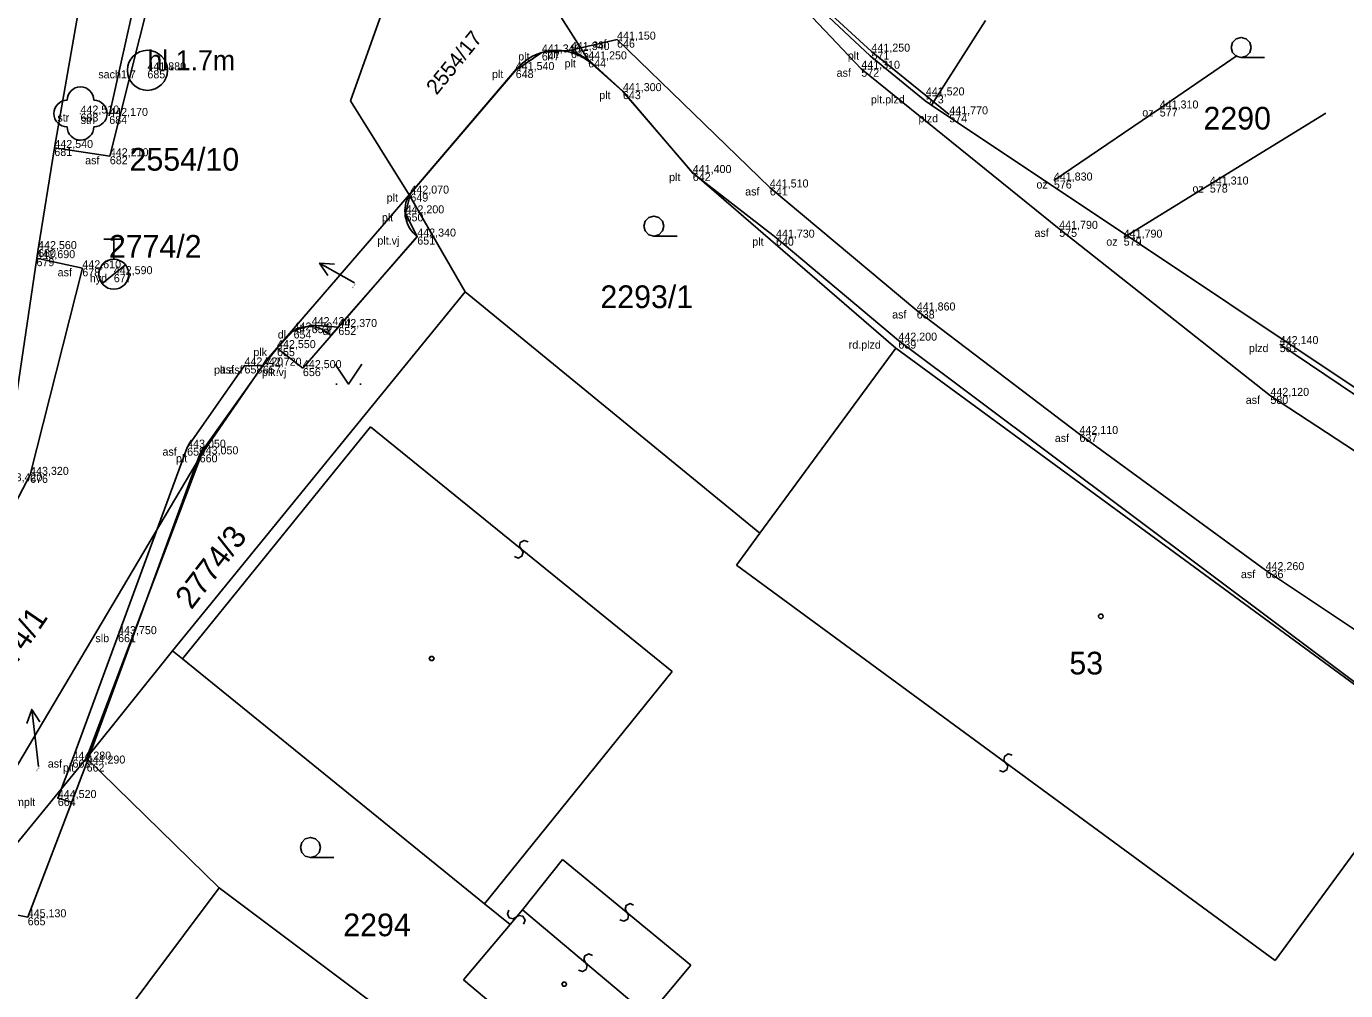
# Model space of a CAD drawing. Extents: x -747792 to -745414, y -1093712 to -1091463.
# Drawn here: x -746697.99 to -746648.52, y -1093147.3 to -1093111.16 of the extents above; entities that cross this region are included whole.
import ezdxf

# ---------------------------------------------------------------- set-up
doc = ezdxf.new("R2010")
doc.units = 0
for name, color, linetype in [('Budovy', 7, 'Continuous'), ('Doplňkové značky', 7, 'Continuous'), ('Hladina', 7, 'Continuous'), ('Koleje_dopravní prvky', 7, 'Continuous'), ('Kultury', 7, 'Continuous'), ('Nezařazené objekty', 7, 'Continuous'), ('Nivelační značky_hrany', 7, 'Continuous'), ('Ploty_opěrné zdi', 7, 'Continuous'), ('Popisy objektů_povrchů', 7, 'Continuous'), ('Pracovní_bod JDTM STC_VC - výška', 7, 'Continuous'), ('Pracovní_bod PPBP - výška', 7, 'Continuous'), ('Pracovní_bod ZPBP - číslo', 7, 'Continuous'), ('Rozhraní ploch', 7, 'Continuous'), ('Stromy_porost', 7, 'Continuous'), ('Výškopis', 7, 'Continuous'), ('Čísla popisná_parcelní', 7, 'Continuous')]:
    doc.layers.add(name, color=color, linetype=linetype)

msp = doc.modelspace()

# ---------------------------------------------------------------- linework, layer by layer
at = {"layer": 'Budovy'}
for points in [[(-746652.44, -1093112.33), (-746652.63, -1093112.28), (-746652.765, -1093112.14), (-746652.815, -1093111.955), (-746652.765, -1093111.77), (-746652.63, -1093111.63), (-746652.44, -1093111.58), (-746652.25, -1093111.63), (-746652.115, -1093111.77), (-746652.065, -1093111.955), (-746652.115, -1093112.14), (-746652.25, -1093112.28), (-746652.44, -1093112.33), (-746651.565, -1093112.33)], [(-746674.46, -1093119.02), (-746674.65, -1093118.97), (-746674.785, -1093118.83), (-746674.835, -1093118.645), (-746674.785, -1093118.46), (-746674.65, -1093118.32), (-746674.46, -1093118.27), (-746674.27, -1093118.32), (-746674.135, -1093118.46), (-746674.085, -1093118.645), (-746674.135, -1093118.83), (-746674.27, -1093118.97), (-746674.46, -1093119.02), (-746673.585, -1093119.02)], [(-746686.41, -1093123.82), (-746685.91, -1093124.57), (-746685.41, -1093123.82)], [(-746686.385, -1093124.57), (-746686.335, -1093124.57)], [(-746685.485, -1093124.57), (-746685.435, -1093124.57)], [(-746687.34, -1093142.31), (-746687.53, -1093142.26), (-746687.665, -1093142.12), (-746687.715, -1093141.935), (-746687.665, -1093141.75), (-746687.53, -1093141.61), (-746687.34, -1093141.56), (-746687.15, -1093141.61), (-746687.015, -1093141.75), (-746686.965, -1093141.935), (-746687.015, -1093142.12), (-746687.15, -1093142.26), (-746687.34, -1093142.31), (-746686.465, -1093142.31)]]:
    msp.add_lwpolyline(points, dxfattribs=at)
at = {"layer": 'Doplňkové značky'}
for points in [[(-746686.996, -1093120.041), (-746685.69, -1093120.78)], [(-746686.683, -1093120.505), (-746686.996, -1093120.041), (-746686.437, -1093120.07)], [(-746697.978, -1093137.287), (-746697.79, -1093136.761), (-746697.482, -1093137.227)], [(-746697.79, -1093136.761), (-746697.61, -1093138.25)], [(-746697.54, -1093138.9), (-746697.61, -1093138.25)]]:
    msp.add_lwpolyline(points, dxfattribs=at)
at = {"layer": 'Hladina'}
for p, q in [((-746677.57, -1093112.05), (-746677.57, -1093112.05)), ((-746675.84, -1093111.66), (-746675.84, -1093111.66)), ((-746666.3, -1093112.11), (-746666.3, -1093112.11)), ((-746678.66, -1093112.14), (-746678.66, -1093112.14)), ((-746676.92, -1093112.4), (-746676.92, -1093112.4)), ((-746693.45, -1093112.81), (-746693.45, -1093112.81)), ((-746679.64, -1093112.8), (-746679.64, -1093112.8)), ((-746666.68, -1093112.75), (-746666.68, -1093112.75)), ((-746675.62, -1093113.59), (-746675.62, -1093113.59)), ((-746664.26, -1093113.75), (-746664.26, -1093113.75)), ((-746695.96, -1093114.43), (-746695.96, -1093114.43)), ((-746694.88, -1093114.52), (-746694.88, -1093114.52)), ((-746663.38, -1093114.46), (-746663.38, -1093114.46)), ((-746655.49, -1093114.24), (-746655.49, -1093114.24)), ((-746696.94, -1093115.72), (-746696.94, -1093115.72)), ((-746694.86, -1093116.03), (-746694.86, -1093116.03)), ((-746673, -1093116.66), (-746673, -1093116.66)), ((-746659.46, -1093116.94), (-746659.46, -1093116.94)), ((-746683.59, -1093117.43), (-746683.59, -1093117.43)), ((-746670.11, -1093117.2), (-746670.11, -1093117.2)), ((-746653.61, -1093117.09), (-746653.61, -1093117.09)), ((-746683.77, -1093118.17), (-746683.77, -1093118.17)), ((-746683.33, -1093119.04), (-746683.33, -1093119.04)), ((-746659.26, -1093118.75), (-746659.26, -1093118.75)), ((-746697.55, -1093119.51), (-746697.55, -1093119.51)), ((-746669.88, -1093119.08), (-746669.88, -1093119.08)), ((-746656.84, -1093119.08), (-746656.84, -1093119.08)), ((-746697.61, -1093119.85), (-746697.61, -1093119.85)), ((-746695.89, -1093120.23), (-746695.89, -1093120.23)), ((-746694.71, -1093120.45), (-746694.71, -1093120.45)), ((-746664.6, -1093121.81), (-746664.6, -1093121.81)), ((-746687.29, -1093122.36), (-746687.29, -1093122.36)), ((-746686.29, -1093122.43), (-746686.29, -1093122.43)), ((-746687.97, -1093122.56), (-746687.97, -1093122.56)), ((-746665.29, -1093122.94), (-746665.29, -1093122.94)), ((-746688.59, -1093123.22), (-746688.59, -1093123.22)), ((-746650.99, -1093123.07), (-746650.99, -1093123.07)), ((-746689.81, -1093123.87), (-746689.81, -1093123.87)), ((-746689.12, -1093123.88), (-746689.12, -1093123.88)), ((-746687.62, -1093123.97), (-746687.62, -1093123.97)), ((-746651.34, -1093125.01), (-746651.34, -1093125.01)), ((-746658.5, -1093126.44), (-746658.5, -1093126.44)), ((-746691.96, -1093126.95), (-746691.96, -1093126.95)), ((-746691.49, -1093127.2), (-746691.49, -1093127.2)), ((-746697.85, -1093127.97), (-746697.85, -1093127.97)), ((-746651.52, -1093131.54), (-746651.52, -1093131.54)), ((-746694.55, -1093133.94), (-746694.55, -1093133.94)), ((-746696.26, -1093138.64), (-746696.26, -1093138.64)), ((-746695.73, -1093138.79), (-746695.73, -1093138.79)), ((-746696.81, -1093140.08), (-746696.81, -1093140.08)), ((-746697.94, -1093144.55), (-746697.94, -1093144.55))]:
    msp.add_line(p, q, dxfattribs=at)
at = {"layer": 'Kultury'}
for points in [[(-746692.14, -1093134.87), (-746685.09, -1093126.17)], [(-746685.09, -1093126.17), (-746673.77, -1093135.34)], [(-746679.175, -1093130.479), (-746679.323, -1093130.424), (-746679.467, -1093130.506), (-746679.497, -1093130.655), (-746679.364, -1093130.873), (-746679.406, -1093131.019), (-746679.551, -1093131.088), (-746679.685, -1093131.031)], [(-746670.48, -1093130.15), (-746671.36, -1093131.36)], [(-746671.36, -1093131.36), (-746651.16, -1093146.17)], [(-746673.77, -1093135.34), (-746680.81, -1093144.04)], [(-746651.16, -1093146.17), (-746645.19, -1093138.03)], [(-746661.018, -1093138.477), (-746661.169, -1093138.429), (-746661.309, -1093138.519), (-746661.332, -1093138.669), (-746661.189, -1093138.879), (-746661.223, -1093139.028), (-746661.365, -1093139.103), (-746661.502, -1093139.053)], [(-746679.39, -1093144.27), (-746677.88, -1093142.39)], [(-746673.07, -1093146.35), (-746677.88, -1093142.39)], [(-746694.77, -1093148.8), (-746690.76, -1093143.45)], [(-746679.348, -1093144.805), (-746679.291, -1093144.658), (-746679.371, -1093144.512), (-746679.519, -1093144.479), (-746679.739, -1093144.609), (-746679.884, -1093144.565), (-746679.951, -1093144.418), (-746679.892, -1093144.285)], [(-746679.39, -1093144.27), (-746679.85, -1093144.82)], [(-746674.66, -1093148.24), (-746679.39, -1093144.27)], [(-746675.733, -1093144.644), (-746675.585, -1093144.7), (-746675.44, -1093144.619), (-746675.408, -1093144.47), (-746675.54, -1093144.252), (-746675.497, -1093144.106), (-746675.351, -1093144.038), (-746675.217, -1093144.096)], [(-746677.285, -1093146.526), (-746677.138, -1093146.584), (-746676.993, -1093146.504), (-746676.959, -1093146.356), (-746677.089, -1093146.136), (-746677.045, -1093145.991), (-746676.898, -1093145.924), (-746676.765, -1093145.984)], [(-746674.66, -1093148.24), (-746673.07, -1093146.35)]]:
    msp.add_lwpolyline(points, dxfattribs=at)
at = {"layer": 'Nezařazené objekty'}
for points in [[(-746664.26, -1093113.75), (-746666.3, -1093112.11), (-746668.1, -1093110.45), (-746670.11, -1093108.19)], [(-746696.94, -1093115.72), (-746696.05, -1093110.64), (-746698.49, -1093109.58)], [(-746683.33, -1093119.04), (-746683.77, -1093118.17), (-746683.59, -1093117.43), (-746679.64, -1093112.8), (-746678.66, -1093112.14), (-746677.57, -1093112.05), (-746676.92, -1093112.4), (-746675.62, -1093113.59), (-746673, -1093116.66), (-746669.88, -1093119.08), (-746665.29, -1093122.94)], [(-746659.46, -1093116.94), (-746655.49, -1093114.24), (-746652.59, -1093112.26)], [(-746663.38, -1093114.46), (-746664.26, -1093113.75)], [(-746656.84, -1093119.08), (-746653.61, -1093117.09), (-746649.26, -1093114.41)], [(-746705.49, -1093140.04), (-746698.84, -1093128.21), (-746697.55, -1093119.51)], [(-746687.62, -1093123.97), (-746688.59, -1093123.22), (-746689.12, -1093123.88), (-746691.49, -1093127.2), (-746695.73, -1093138.79), (-746697.94, -1093144.55)], [(-746621.41, -1093142.89), (-746630.66, -1093136.76), (-746650.99, -1093123.07)]]:
    msp.add_lwpolyline(points, dxfattribs=at)
at = {"layer": 'Nivelační značky_hrany'}
for points in [[(-746660.99, -1093060), (-746658.44, -1093054.36), (-746660.29, -1093053.55), (-746661.8, -1093053.25), (-746663.42, -1093053.5), (-746664.3, -1093053.85), (-746664.96, -1093054.44), (-746666.14, -1093054.24), (-746674.99, -1093068.6), (-746677.6, -1093073.69), (-746678.64, -1093076.35), (-746679.29, -1093079.05), (-746679.71, -1093081.48), (-746679.69, -1093086.54), (-746679.06, -1093091.02), (-746678.19, -1093094.74), (-746676.83, -1093098.38), (-746673.81, -1093104.16), (-746670.33, -1093108.89), (-746666.68, -1093112.75), (-746659.26, -1093118.75), (-746651.34, -1093125.01), (-746630.74, -1093138.49)], [(-746696.94, -1093115.72), (-746694.86, -1093116.03), (-746693.01, -1093108.68), (-746692.13, -1093105.25), (-746690.31, -1093098.38), (-746694.28, -1093095.9)], [(-746632.95, -1093144.66), (-746633.15, -1093143.59), (-746640.24, -1093139.06), (-746651.52, -1093131.54), (-746658.5, -1093126.44), (-746664.6, -1093121.81), (-746670.11, -1093117.2), (-746675.84, -1093111.66), (-746677.57, -1093112.05)], [(-746702.56, -1093143.65), (-746702.03, -1093140.76), (-746701.01, -1093138.6), (-746702.96, -1093137.84), (-746702.2, -1093136.25), (-746697.85, -1093127.97), (-746695.89, -1093120.23), (-746697.61, -1093119.85)], [(-746686.29, -1093122.43), (-746687.29, -1093122.36), (-746687.97, -1093122.56), (-746688.59, -1093123.22)], [(-746696.29, -1093140.24), (-746696.81, -1093140.08), (-746696.26, -1093138.64), (-746691.96, -1093126.95), (-746689.81, -1093123.87), (-746689.12, -1093123.88)]]:
    msp.add_lwpolyline(points, dxfattribs=at)
at = {"layer": 'Ploty_opěrné zdi'}
for points in [[(-746657.7, -1093133.185), (-746657.65, -1093133.195), (-746657.625, -1093133.24), (-746657.615, -1093133.27), (-746657.625, -1093133.315), (-746657.665, -1093133.35), (-746657.7, -1093133.355), (-746657.745, -1093133.34), (-746657.775, -1093133.31), (-746657.785, -1093133.27), (-746657.775, -1093133.225), (-746657.735, -1093133.19)], [(-746682.745, -1093134.775), (-746682.7, -1093134.85), (-746682.745, -1093134.925), (-746682.835, -1093134.925), (-746682.88, -1093134.85), (-746682.835, -1093134.775)], [(-746677.775, -1093146.985), (-746677.73, -1093147.06), (-746677.775, -1093147.135), (-746677.865, -1093147.135), (-746677.91, -1093147.06), (-746677.865, -1093146.985)]]:
    msp.add_lwpolyline(points, close=True, dxfattribs=at)
at = {"layer": 'Popisy objektů_povrchů'}
msp.add_lwpolyline([(-746665.29, -1093122.94), (-746645.12, -1093138.03)], dxfattribs=at)
at = {"layer": 'Pracovní_bod JDTM STC_VC - výška'}
msp.add_lwpolyline([(-746693.82, -1093109.75), (-746694.88, -1093114.52)], dxfattribs=at)
msp.add_circle((-746695.96, -1093114.43), 0.0005, dxfattribs=at)
for centre, start, end in [((-746695.96, -1093113.93), 0, 180), ((-746696.46, -1093114.43), 90, 270), ((-746695.46, -1093114.43), 270, 90), ((-746695.96, -1093114.93), 180, 360)]:
    msp.add_arc(centre, 0.5, start, end, dxfattribs=at)
at = {"layer": 'Pracovní_bod PPBP - výška'}
for points in [[(-746697.55, -1093119.51), (-746696.94, -1093115.72)], [(-746683.33, -1093119.04), (-746687.62, -1093123.97)], [(-746697.94, -1093144.55), (-746702.05, -1093143.72)]]:
    msp.add_lwpolyline(points, dxfattribs=at)
at = {"layer": 'Stromy_porost'}
for points in [[(-746685.84, -1093113.95), (-746682.29, -1093103.98)], [(-746682.29, -1093103.98), (-746676.87, -1093112.49)], [(-746668.1, -1093110.63), (-746666.35, -1093112.27)], [(-746662.02, -1093110.94), (-746664.05, -1093114.11)], [(-746676.87, -1093112.49), (-746675.62, -1093113.6), (-746673.04, -1093116.62)], [(-746666.35, -1093112.27), (-746664.29, -1093113.95)], [(-746683.64, -1093117.48), (-746679.61, -1093112.76)], [(-746683.64, -1093117.48), (-746685.84, -1093113.95)], [(-746664.05, -1093114.11), (-746664.29, -1093113.95)], [(-746641.71, -1093129), (-746664.05, -1093114.11)], [(-746673.04, -1093116.62), (-746665.39, -1093123.22)], [(-746688.2, -1093122.76), (-746683.64, -1093117.48)], [(-746681.53, -1093121.11), (-746683.64, -1093117.48)], [(-746686.63, -1093122.7), (-746686.57, -1093122.75), (-746683.33, -1093119.05), (-746683.41, -1093118.98)], [(-746681.53, -1093121.11), (-746692.51, -1093134.57)], [(-746670.48, -1093130.15), (-746681.53, -1093121.11)], [(-746688.2, -1093122.76), (-746689, -1093123.69)], [(-746665.39, -1093123.22), (-746670.48, -1093130.15)], [(-746665.39, -1093123.22), (-746645.19, -1093138.03)], [(-746689, -1093123.69), (-746691.42, -1093127.21)], [(-746701.08, -1093143.48), (-746691.42, -1093127.21)], [(-746695.73, -1093138.59), (-746691.42, -1093127.21)], [(-746692.51, -1093134.57), (-746695.73, -1093138.59)], [(-746692.14, -1093134.87), (-746692.51, -1093134.57)], [(-746692.14, -1093134.87), (-746680.81, -1093144.04)], [(-746695.73, -1093138.59), (-746700.16, -1093143.98)], [(-746695.73, -1093138.59), (-746690.76, -1093143.45)], [(-746690.76, -1093143.45), (-746678.41, -1093152.7)], [(-746680.81, -1093144.04), (-746679.85, -1093144.82)], [(-746679.85, -1093144.82), (-746681.6, -1093146.9)], [(-746681.6, -1093146.9), (-746676.87, -1093150.87)]]:
    msp.add_lwpolyline(points, dxfattribs=at)
for centre, radius, start, end in [((-746678.101, -1093114.04), 1.979, 51.5536, 139.7019), ((-746682.55, -1093118.081), 1.244, 151.1429, 226.292), ((-746687.384, -1093123.532), 1.123, 47.8191, 136.5581)]:
    msp.add_arc(centre, radius, start, end, dxfattribs=at)
at = {"layer": 'Čísla popisná_parcelní'}
for p, q in [((-746695.085, -1093119.137), (-746694.335, -1093119.137)), ((-746694.71, -1093119.887), (-746694.71, -1093119.137)), ((-746695.151, -1093120.796), (-746694.266, -1093120.102))]:
    msp.add_line(p, q, dxfattribs=at)
for centre, radius in [((-746693.45, -1093112.81), 0.75), ((-746694.71, -1093120.45), 0.562)]:
    msp.add_circle(centre, radius, dxfattribs=at)

# ---------------------------------------------------------------- texts
at = {"layer": 'Doplňkové značky'}
msp.add_text('2774/2', height=0.85, dxfattribs=at).set_placement((-746694.895, -1093119.83))
msp.add_text('2774/1', height=0.85, rotation=55.6915, dxfattribs=at).set_placement((-746699.112, -1093136.176))
at = {"layer": 'Koleje_dopravní prvky'}
for s, height, rotation, p in [('2554/17', 0.57, 50.7068, (-746682.605, -1093113.761)), ('2774/2', 0.05, 57.4677, (-746685.74, -1093120.99)), ('2774/3', 0.85, 52.4256, (-746691.8, -1093133.05)), ('2774/1', 0.05, 57.4677, (-746697.59, -1093139.1))]:
    msp.add_text(s, height=height, rotation=rotation, dxfattribs=at).set_placement(p)
for s, p in [('2290', (-746653.849, -1093115.03)), ('2554/10', (-746694.119, -1093116.57)), ('2293/1', (-746676.464, -1093121.72)), ('53', (-746658.879, -1093135.45)), ('2294', (-746686.105, -1093145.26))]:
    msp.add_text(s, height=0.85, dxfattribs=at).set_placement(p)
at = {"layer": 'Pracovní_bod ZPBP - číslo'}
msp.add_text('hl.1.7m', height=0.75, dxfattribs=at).set_placement((-746693.45, -1093112.81))
at = {"layer": 'Rozhraní ploch'}
for s, p in [(' plt', (-746679.659, -1093112.44)), ('647', (-746678.66, -1093112.44)), (' plt', (-746678.569, -1093112.35)), ('645', (-746677.57, -1093112.35)), (' asf', (-746676.877, -1093111.96)), ('646', (-746675.84, -1093111.96)), (' plt', (-746667.299, -1093112.41)), ('571', (-746666.3, -1093112.41)), (' plt', (-746677.919, -1093112.7)), ('644', (-746676.92, -1093112.7)), (' sach1.7', (-746695.403, -1093113.11)), ('685', (-746693.45, -1093113.11)), (' plt', (-746680.639, -1093113.1)), ('648', (-746679.64, -1093113.1)), (' asf', (-746667.717, -1093113.05)), ('572', (-746666.68, -1093113.05)), (' plt', (-746676.619, -1093113.89)), ('643', (-746675.62, -1093113.89)), (' plt.plzd', (-746666.433, -1093114.05)), ('573', (-746664.26, -1093114.05)), (' str', (-746696.938, -1093114.73)), (' strl', (-746696.066, -1093114.82)), ('683', (-746695.96, -1093114.73)), ('684', (-746694.88, -1093114.82)), (' plzd', (-746664.648, -1093114.76)), ('574', (-746663.38, -1093114.76)), (' oz', (-746656.255, -1093114.54)), ('577', (-746655.49, -1093114.54)), ('681', (-746696.94, -1093116.02)), (' asf', (-746695.897, -1093116.33)), ('682', (-746694.86, -1093116.33)), (' plt', (-746673.999, -1093116.96)), ('642', (-746673, -1093116.96)), (' oz', (-746660.225, -1093117.24)), ('576', (-746659.46, -1093117.24)), (' plt', (-746684.589, -1093117.73)), ('649', (-746683.59, -1093117.73)), (' asf', (-746671.147, -1093117.5)), ('641', (-746670.11, -1093117.5)), (' oz', (-746654.375, -1093117.39)), ('578', (-746653.61, -1093117.39)), (' plt', (-746684.769, -1093118.47)), ('650', (-746683.77, -1093118.47)), (' plt.vj', (-746684.938, -1093119.34)), ('651', (-746683.33, -1093119.34)), (' asf', (-746660.297, -1093119.05)), ('575', (-746659.26, -1093119.05)), ('680', (-746697.55, -1093119.81)), (' plt', (-746670.879, -1093119.38)), ('640', (-746669.88, -1093119.38)), (' oz', (-746657.605, -1093119.38)), ('579', (-746656.84, -1093119.38)), ('679', (-746697.61, -1093120.15)), (' asf', (-746696.927, -1093120.53)), ('678', (-746695.89, -1093120.53)), (' hyd', (-746695.721, -1093120.75)), ('677', (-746694.71, -1093120.75)), (' asf', (-746665.637, -1093122.11)), ('638', (-746664.6, -1093122.11)), (' dl', (-746687.994, -1093122.66)), ('653', (-746687.29, -1093122.66)), (' dl', (-746686.994, -1093122.73)), ('652', (-746686.29, -1093122.73)), (' dl', (-746688.674, -1093122.86)), ('654', (-746687.97, -1093122.86)), (' rd.plzd', (-746667.264, -1093123.24)), ('639', (-746665.29, -1093123.24)), (' plk', (-746689.589, -1093123.52)), ('655', (-746688.59, -1093123.52)), (' plzd', (-746652.258, -1093123.37)), ('581', (-746650.99, -1093123.37)), (' plt.asf', (-746691.061, -1093124.18)), (' asf', (-746690.847, -1093124.17)), ('658', (-746689.81, -1093124.17)), (' plk.vj', (-746689.269, -1093124.27)), ('657', (-746689.12, -1093124.18)), ('656', (-746687.62, -1093124.27)), (' asf', (-746652.377, -1093125.31)), ('580', (-746651.34, -1093125.31)), (' asf', (-746659.537, -1093126.74)), ('637', (-746658.5, -1093126.74)), (' asf', (-746692.997, -1093127.25)), ('659', (-746691.96, -1093127.25)), (' plt', (-746692.489, -1093127.5)), ('660', (-746691.49, -1093127.5)), ('676', (-746697.85, -1093128.27)), (' asf', (-746652.557, -1093131.84)), ('636', (-746651.52, -1093131.84)), (' slb', (-746695.511, -1093134.24)), ('661', (-746694.55, -1093134.24)), (' asf', (-746697.297, -1093138.94)), (' plt', (-746696.729, -1093139.09)), ('663', (-746696.26, -1093138.94)), ('662', (-746695.73, -1093139.09)), (' asf.smplt', (-746699.375, -1093140.38)), ('664', (-746696.81, -1093140.38)), ('665', (-746697.94, -1093144.85))]:
    msp.add_text(s, height=0.3, dxfattribs=at).set_placement(p)
at = {"layer": 'Výškopis'}
for s, p in [('441,150', (-746675.84, -1093111.66)), ('441,340', (-746678.66, -1093112.14)), ('441,340', (-746677.57, -1093112.05)), ('441,250', (-746676.92, -1093112.4)), ('441,250', (-746666.3, -1093112.11)), ('441,880', (-746693.45, -1093112.81)), ('441,540', (-746679.64, -1093112.8)), ('441,310', (-746666.68, -1093112.75)), ('441,300', (-746675.62, -1093113.59)), ('441,520', (-746664.26, -1093113.75)), ('441,310', (-746655.49, -1093114.24)), ('442,510', (-746695.96, -1093114.43)), ('442,170', (-746694.88, -1093114.52)), ('441,770', (-746663.38, -1093114.46)), ('442,540', (-746696.94, -1093115.72)), ('442,210', (-746694.86, -1093116.03)), ('441,400', (-746673, -1093116.66)), ('441,510', (-746670.11, -1093117.2)), ('441,830', (-746659.46, -1093116.94)), ('441,310', (-746653.61, -1093117.09)), ('442,070', (-746683.59, -1093117.43)), ('442,200', (-746683.77, -1093118.17)), ('441,790', (-746659.26, -1093118.75)), ('442,340', (-746683.33, -1093119.04)), ('441,730', (-746669.88, -1093119.08)), ('441,790', (-746656.84, -1093119.08)), ('442,690', (-746697.61, -1093119.85)), ('442,560', (-746697.55, -1093119.51)), ('442,610', (-746695.89, -1093120.23)), ('442,590', (-746694.71, -1093120.45)), ('441,860', (-746664.6, -1093121.81)), ('442,570', (-746687.97, -1093122.56)), ('442,430', (-746687.29, -1093122.36)), ('442,370', (-746686.29, -1093122.43)), ('442,550', (-746688.59, -1093123.22)), ('442,200', (-746665.29, -1093122.94)), ('442,140', (-746650.99, -1093123.07)), ('442,720', (-746689.81, -1093123.87)), ('442,720', (-746689.12, -1093123.88)), ('442,500', (-746687.62, -1093123.97)), ('442,120', (-746651.34, -1093125.01)), ('442,110', (-746658.5, -1093126.44)), ('443,050', (-746691.96, -1093126.95)), ('443,050', (-746691.49, -1093127.2)), ('443,420', (-746698.84, -1093128.21)), ('443,320', (-746697.85, -1093127.97)), ('442,260', (-746651.52, -1093131.54)), ('443,750', (-746694.55, -1093133.94)), ('444,280', (-746696.26, -1093138.64)), ('444,290', (-746695.73, -1093138.79)), ('444,520', (-746696.81, -1093140.08)), ('445,130', (-746697.94, -1093144.55))]:
    msp.add_text(s, height=0.3, dxfattribs=at).set_placement(p)

doc.saveas('drawing.dxf')
